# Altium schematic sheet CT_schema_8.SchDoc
size 278 x 170 mm
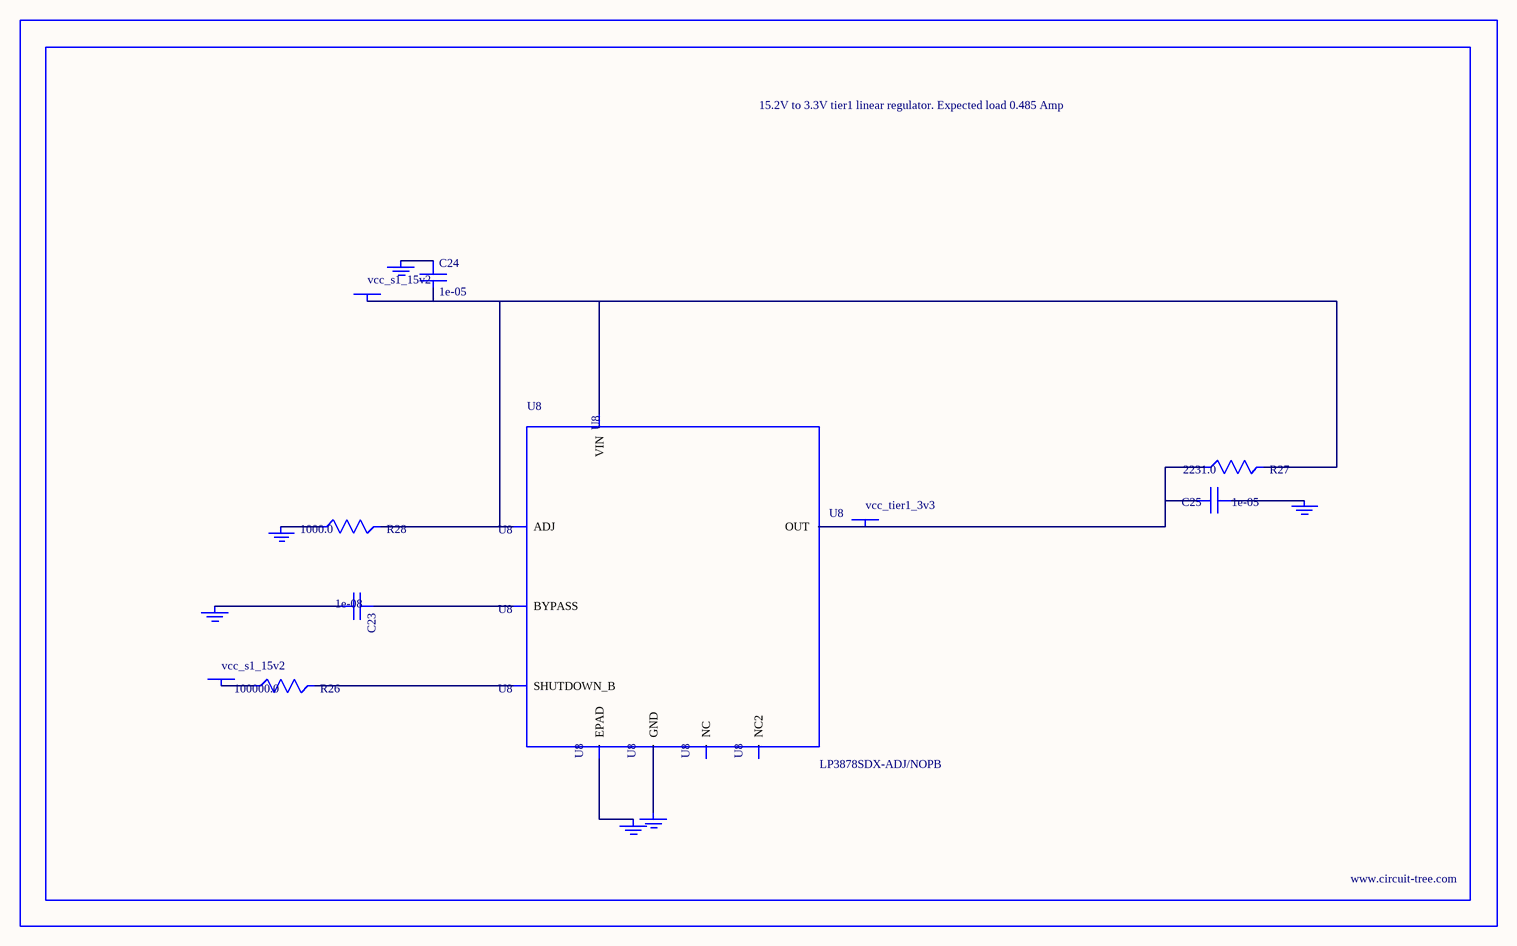
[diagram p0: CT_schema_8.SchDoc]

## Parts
BORDER7  (no value)
C23  1e-08  [C0402]
C24  1e-05  [C1210]
C25  1e-05  [C1210]
GND_INSTANCE_7_0  (no value)
GND_INSTANCE_7_1  (no value)
GND_INSTANCE_7_2  (no value)
GND_INSTANCE_7_3  (no value)
GND_INSTANCE_7_4  (no value)
GND_INSTANCE_7_5  (no value)
POWER_INSTANCE_7_0  vcc_s1_15v2
POWER_INSTANCE_7_1  vcc_s1_15v2
POWER_INSTANCE_7_2  vcc_tier1_3v3
R26  100000.0  [R0603]
R27  2231.0  [R0603]
R28  1000.0  [R0603]
U8  LP3878SDX-ADJ/NOPB  [WSON-8]

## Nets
NetC23_1: C23.1 U8.1(BYPASS)
NetC23_2: C23.2 GND_INSTANCE_7_0.0(GND)
NetC24_1: C24.1 GND_INSTANCE_7_1.0(GND)
NetC24_2: C24.2 POWER_INSTANCE_7_0.0(PWR) R27.2 R28.2 U8.4(VIN) U8.6(ADJ)
NetC25_1: C25.1 GND_INSTANCE_7_2.0(GND)
NetC25_2: C25.2 POWER_INSTANCE_7_2.0(PWR) R27.1 U8.5(OUT)
NetGND_INSTANCE_7_3_0: GND_INSTANCE_7_3.0(GND) R28.1
NetGND_INSTANCE_7_4_0: GND_INSTANCE_7_4.0(GND) U8.PAD(EPAD)
NetGND_INSTANCE_7_5_0: GND_INSTANCE_7_5.0(GND) U8.3(GND)
NetPOWER_INSTANCE_7_1_0: POWER_INSTANCE_7_1.0(PWR) R26.1
NetR26_2: R26.2 U8.8(SHUTDOWN_B)

Not connected (* = marked no-connect by the designer): U8 2(NC) 7(NC2)

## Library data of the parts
BORDER7 = BORDER_PAGE7
C23 = C0402C103K3RAC
C24 = C1210C106K5PACTU
C25 = GRM32DR61E106MA12L
GND_INSTANCE_7_0-GND_INSTANCE_7_5 = GND
POWER_INSTANCE_7_0-POWER_INSTANCE_7_2 = PWR
R26 = RC0603JR-07100KL
R27 = R27
R28 = RC0603JR-071KL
